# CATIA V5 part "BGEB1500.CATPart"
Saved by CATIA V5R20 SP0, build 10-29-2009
Part number: BGEB1500
Revision: 3
Definition: design
Nomenclature: BGEB1500
Source: made
Description: NOT SPECIFIED
Bounding box of the stored display mesh (mm): x -34.125 to 34.125, y -34.125 to 34.125, z -16.002 to 41.148
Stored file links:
  C:\Users\Utente\Desktop\3D files BGEB\BGEB1500.CATPart
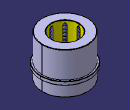
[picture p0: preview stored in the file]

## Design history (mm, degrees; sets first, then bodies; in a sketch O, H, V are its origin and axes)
Body1 "MANIFOLD_SOLID_BREP #38" (main body)
  Solid1: solid without history
Body2 "MANIFOLD_SOLID_BREP #76"
  Solid2: solid without history
Body3 "MANIFOLD_SOLID_BREP #114"
  Solid3: solid without history
Body4 "MANIFOLD_SOLID_BREP #152"
  Solid4: solid without history
Body5 "MANIFOLD_SOLID_BREP #190"
  Solid5: solid without history
Body6 "MANIFOLD_SOLID_BREP #228"
  Solid6: solid without history
Body7 "MANIFOLD_SOLID_BREP #266"
  Solid7: solid without history
Body8 "MANIFOLD_SOLID_BREP #304"
  Solid8: solid without history
Body9 "MANIFOLD_SOLID_BREP #2384"
  Solid9: solid without history
Body10 "MANIFOLD_SOLID_BREP #2422"
  Solid10: solid without history
Body11 "MANIFOLD_SOLID_BREP #2460"
  Solid11: solid without history
Body12 "MANIFOLD_SOLID_BREP #2498"
  Solid12: solid without history
Body13 "MANIFOLD_SOLID_BREP #2536"
  Solid13: solid without history
Body14 "MANIFOLD_SOLID_BREP #2574"
  Solid14: solid without history
Body15 "MANIFOLD_SOLID_BREP #2612"
  Solid15: solid without history
Body16 "MANIFOLD_SOLID_BREP #2650"
  Solid16: solid without history
Body17 "MANIFOLD_SOLID_BREP #2688"
  Solid17: solid without history
Body18 "MANIFOLD_SOLID_BREP #2726"
  Solid18: solid without history
Body19 "MANIFOLD_SOLID_BREP #2764"
  Solid19: solid without history
Body20 "MANIFOLD_SOLID_BREP #2802"
  Solid20: solid without history
Body21 "MANIFOLD_SOLID_BREP #2840"
  Solid21: solid without history
Body22 "MANIFOLD_SOLID_BREP #2878"
  Solid22: solid without history
Body23 "MANIFOLD_SOLID_BREP #2916"
  Solid23: solid without history
Body24 "MANIFOLD_SOLID_BREP #2954"
  Solid24: solid without history
Body25 "MANIFOLD_SOLID_BREP #2992"
  Solid25: solid without history
Body26 "MANIFOLD_SOLID_BREP #3030"
  Solid26: solid without history
Body27 "MANIFOLD_SOLID_BREP #3068"
  Solid27: solid without history
Body28 "MANIFOLD_SOLID_BREP #3106"
  Solid28: solid without history
Body29 "MANIFOLD_SOLID_BREP #3144"
  Solid29: solid without history
Body30 "MANIFOLD_SOLID_BREP #3182"
  Solid30: solid without history
Body31 "MANIFOLD_SOLID_BREP #3220"
  Solid31: solid without history
Body32 "MANIFOLD_SOLID_BREP #3258"
  Solid32: solid without history
Body33 "MANIFOLD_SOLID_BREP #3296"
  Solid33: solid without history
Body34 "MANIFOLD_SOLID_BREP #3334"
  Solid34: solid without history
Body35 "MANIFOLD_SOLID_BREP #3372"
  Solid35: solid without history
Body36 "MANIFOLD_SOLID_BREP #3410"
  Solid36: solid without history
Body37 "MANIFOLD_SOLID_BREP #3448"
  Solid37: solid without history
Body38 "MANIFOLD_SOLID_BREP #3486"
  Solid38: solid without history
Body39 "MANIFOLD_SOLID_BREP #3524"
  Solid39: solid without history
Body40 "MANIFOLD_SOLID_BREP #3562"
  Solid40: solid without history
Body41 "MANIFOLD_SOLID_BREP #3600"
  Solid41: solid without history
Body42 "MANIFOLD_SOLID_BREP #3638"
  Solid42: solid without history
Body43 "MANIFOLD_SOLID_BREP #3676"
  Solid43: solid without history
Body44 "MANIFOLD_SOLID_BREP #3714"
  Solid44: solid without history
Body45 "MANIFOLD_SOLID_BREP #3752"
  Solid45: solid without history
Body46 "MANIFOLD_SOLID_BREP #3790"
  Solid46: solid without history
Body47 "MANIFOLD_SOLID_BREP #3828"
  Solid47: solid without history
Body48 "MANIFOLD_SOLID_BREP #3866"
  Solid48: solid without history
Body49 "MANIFOLD_SOLID_BREP #3904"
  Solid49: solid without history
Body50 "MANIFOLD_SOLID_BREP #3942"
  Solid50: solid without history
Body51 "MANIFOLD_SOLID_BREP #3980"
  Solid51: solid without history
Body52 "MANIFOLD_SOLID_BREP #4018"
  Solid52: solid without history
Body53 "MANIFOLD_SOLID_BREP #4056"
  Solid53: solid without history
Body54 "MANIFOLD_SOLID_BREP #4094"
  Solid54: solid without history
Body55 "MANIFOLD_SOLID_BREP #4132"
  Solid55: solid without history
Body56 "MANIFOLD_SOLID_BREP #4170"
  Solid56: solid without history
Body57 "MANIFOLD_SOLID_BREP #4208"
  Solid57: solid without history
Body58 "MANIFOLD_SOLID_BREP #4246"
  Solid58: solid without history
Body59 "MANIFOLD_SOLID_BREP #4284"
  Solid59: solid without history
Body60 "MANIFOLD_SOLID_BREP #4322"
  Solid60: solid without history
Body61 "MANIFOLD_SOLID_BREP #4360"
  Solid61: solid without history
Body62 "MANIFOLD_SOLID_BREP #4398"
  Solid62: solid without history
Body63 "MANIFOLD_SOLID_BREP #4436"
  Solid63: solid without history
Body64 "MANIFOLD_SOLID_BREP #4474"
  Solid64: solid without history
Body65 "MANIFOLD_SOLID_BREP #4512"
  Solid65: solid without history
Body66 "MANIFOLD_SOLID_BREP #4550"
  Solid66: solid without history
Body67 "MANIFOLD_SOLID_BREP #4588"
  Solid67: solid without history
Body68 "MANIFOLD_SOLID_BREP #4626"
  Solid68: solid without history
Body69 "MANIFOLD_SOLID_BREP #4664"
  Solid69: solid without history
Body70 "MANIFOLD_SOLID_BREP #4702"
  Solid70: solid without history
Body71 "MANIFOLD_SOLID_BREP #4740"
  Solid71: solid without history
Body72 "MANIFOLD_SOLID_BREP #4778"
  Solid72: solid without history
Body73 "MANIFOLD_SOLID_BREP #4816"
  Solid73: solid without history
Body74 "MANIFOLD_SOLID_BREP #4854"
  Solid74: solid without history
Body75 "MANIFOLD_SOLID_BREP #4892"
  Solid75: solid without history
Body76 "MANIFOLD_SOLID_BREP #4930"
  Solid76: solid without history
Body77 "MANIFOLD_SOLID_BREP #4968"
  Solid77: solid without history
Body78 "MANIFOLD_SOLID_BREP #5006"
  Solid78: solid without history
Body79 "MANIFOLD_SOLID_BREP #5044"
  Solid79: solid without history
Body80 "MANIFOLD_SOLID_BREP #5082"
  Solid80: solid without history
Body81 "MANIFOLD_SOLID_BREP #5120"
  Solid81: solid without history
Body82 "MANIFOLD_SOLID_BREP #5158"
  Solid82: solid without history
Body83 "MANIFOLD_SOLID_BREP #5196"
  Solid83: solid without history
Body84 "MANIFOLD_SOLID_BREP #5234"
  Solid84: solid without history
Body85 "MANIFOLD_SOLID_BREP #5272"
  Solid85: solid without history
Body86 "MANIFOLD_SOLID_BREP #5310"
  Solid86: solid without history
Body87 "MANIFOLD_SOLID_BREP #5348"
  Solid87: solid without history
Body88 "MANIFOLD_SOLID_BREP #5386"
  Solid88: solid without history
Body89 "MANIFOLD_SOLID_BREP #5424"
  Solid89: solid without history
Body90 "MANIFOLD_SOLID_BREP #5462"
  Solid90: solid without history
Body91 "MANIFOLD_SOLID_BREP #5500"
  Solid91: solid without history
Body92 "MANIFOLD_SOLID_BREP #5538"
  Solid92: solid without history
Body93 "MANIFOLD_SOLID_BREP #5576"
  Solid93: solid without history
Body94 "MANIFOLD_SOLID_BREP #5614"
  Solid94: solid without history
Body95 "MANIFOLD_SOLID_BREP #5652"
  Solid95: solid without history
Body96 "MANIFOLD_SOLID_BREP #5690"
  Solid96: solid without history
Body97 "MANIFOLD_SOLID_BREP #5728"
  Solid97: solid without history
